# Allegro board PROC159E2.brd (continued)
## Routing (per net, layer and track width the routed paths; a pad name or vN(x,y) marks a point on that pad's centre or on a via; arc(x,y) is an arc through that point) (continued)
ICSSM_MII0_RXD3_ADD: length 27.5
  TOP w0.147: R536.1 76.94,70.68 76.53,71.09 76.52,71.09 76.49,71.11 75.8,71.11 v1(75.34,70.66)
  L08_SIG2 w0.091: v1(72.17,57.89) 70.63,57.89 70.28,58.24 70.28,64.26 68.91,65.63 68.91,71.68 69.33,72.1 70.54,72.1 71.37,71.27 73.53,71.27 73.66,71.13 73.66,70.99 73.79,70.86 73.98,70.86 74.12,70.99 74.12,71.13 74.25,71.27 74.74,71.27 v1(75.34,70.66)
  BOTTOM w0.147: v1(72.17,57.89) U82.35
ICSSM_MII0_RXD3_ON: length 58.2
  TOP w0.147: R480.1 85.23,78.27 85.43,78.46 v1(85.43,79.32)
  L03_SIG1 w0.091: v1(85.43,79.32) 85.93,78.82 85.93,78.03 85,77.09 85,75.9 85.93,74.96 85.93,74.61 86.79,73.75 86.79,71.06 86.36,70.62 86.36,68.44 85.96,68.04 84.56,68.04 84.46,67.93 84.46,67.78 84.56,67.67 85.82,67.67 85.93,67.57 85.93,67.41 85.82,67.31 84.56,67.31 84.46,67.2 84.46,67.05 84.56,66.94 85.5,66.94 85.93,66.51 85.93,65.8 85.57,65.44 82.61,65.44 82.49,65.55 82.49,65.77 82.61,65.89 85.38,65.89 85.52,66.03 85.52,66.25 85.38,66.39 82.31,66.39 82.12,66.57 81.13,66.57 79.72,67.97 79.72,69.59 79.17,70.14 77.46,70.14 77.06,69.73 77.06,69.35 75.85,68.14 74.03,68.14 70.27,64.38 70.27,58.12 70.73,57.66 70.99,57.66 v1(71.25,57.39)
  BOTTOM w0.147: U82.36 v1(71.25,57.39)
ICSSM_MII0_RXDV: length 17.3
  TOP w0.147: U87.34 73.79,58.39 73.41,58.02 73.41,57.87 73.22,57.68 72.91,57.68 72.78,57.81 72.78,58.04 73.42,58.68 73.42,58.94 73.27,59.08 72.78,59.08 72.62,58.93 72.62,58.58 72.43,58.39 72.01,58.39 71.51,58.89 71.04,58.89 70.71,58.56 70.71,58.22 70.58,58.09 70.39,58.09 70.27,58.22 70.27,58.77 70.56,59.07 70.56,59.25 70.41,59.4 70.19,59.4 70.01,59.22 70.01,59.04 69.6,58.63 67.76,58.63 67.58,58.45 67.22,58.45 66.96,58.71 66.96,58.93 67.1,59.07 67.3,59.07 67.42,59.19 67.42,59.31 67.29,59.45 66.31,59.45 66.18,59.31 v1(66.18,58.89)
  BOTTOM w0.147: U82.6 v1(66.18,58.89)
ICSSM_MII0_RXDV_ADD: length 27.9
  L08_SIG2 w0.091: v1(72.17,58.89) 70.98,58.89 70.55,59.32 70.55,64.38 69.18,65.74 69.18,70.81 69.64,71.26 70.78,71.26 71.91,70.14 75.91,70.14 76.38,69.67 v1(78.54,69.67)
  BOTTOM w0.147: v1(72.17,58.89) U82.33 ; R537.1 76.88,69.66 77.33,69.21 78.16,69.21 v1(78.54,69.67)
ICSSM_MII0_RXDV_ON: length 57.8
  TOP w0.147: R481.1 v1(97.63,94.93)
  L08_SIG2 w0.091: v1(97.63,94.93) 98.67,93.9 98.67,90.09 97.71,89.12 97.71,83.8 95.88,81.98 94.98,81.98 94.06,81.05 90.24,81.05 86.83,77.65 86.83,76.22 85.9,75.29 85.19,75.29 84.74,75.74 84.42,75.74 83.26,74.58 83.26,71.71 81.51,69.96 81.51,63.2 80.41,62.11 80.41,61.74 79.46,60.78 79.46,60.4 77.72,58.67 75.21,58.67 74.94,58.39 v1(71.25,58.39)
  BOTTOM w0.147: U82.34 v1(71.25,58.39)
ICSSM_MII0_RXER: length 16.6
  TOP w0.147: v1(64.5,59.39) 63.55,59.39 63.35,59.2 63.35,58.77 63.53,58.6 64.71,58.6 65.87,59.76 70.98,59.76 71.06,59.85 71.5,59.85 71.95,59.39 U87.32
  BOTTOM w0.147: U82.7 65.94,59.39 65.61,59.07 64.83,59.07 v1(64.5,59.39)
ICSSM_MII0_RXER_ADD: length 28
  L08_SIG2 w0.091: v1(78.54,68.68) 78.06,69.16 75.08,69.16 74.38,69.86 73.93,69.86 73.8,69.73 73.8,69.48 73.66,69.35 73.47,69.35 73.34,69.48 73.34,69.73 73.2,69.86 73.01,69.86 72.88,69.73 72.88,69.48 72.75,69.35 72.56,69.35 72.42,69.48 72.42,69.73 72.29,69.86 71.75,69.86 70.62,70.99 69.75,70.99 69.46,70.7 69.46,65.86 70.82,64.49 70.82,60.15 71.08,59.89 v1(72.17,59.89)
  BOTTOM w0.147: R538.1 76.88,68.67 77.33,68.22 78.16,68.22 v1(78.54,68.68) ; v1(72.17,59.89) U82.31
ICSSM_MII0_RXER_ON: length 57.5
  TOP w0.147: R482.1 v1(97.63,93.94)
  L08_SIG2 w0.091: v1(71.25,59.39) 72.62,59.39 72.72,59.29 72.72,58.71 72.83,58.61 72.98,58.61 73.09,58.71 73.09,59.29 73.2,59.39 74.84,59.39 75.23,59.78 77.43,59.78 78.76,61.1 79.06,61.1 79.48,61.53 79.48,62.06 79.76,62.35 80.39,62.35 81.25,63.2 81.25,70.07 83,71.82 83,74.63 84.37,76 84.9,76 85.37,75.54 85.76,75.54 86.61,76.39 86.61,77.71 90.15,81.26 93.94,81.26 94.89,82.2 95.72,82.2 97.47,83.95 97.47,89.27 98.39,90.2 98.39,93.76 98.21,93.94 v1(97.63,93.94)
  BOTTOM w0.147: U82.32 v1(71.25,59.39)
ICSSM_MII0_RXLINK: length 16.6
  TOP w0.147: U87.27 72.77,61.89 72.61,62.06 72.61,62.27 72.73,62.39 73.3,62.39 73.44,62.54 73.44,62.8 72.64,63.61 72.64,64.72 72.3,65.06 71.38,65.06 71.09,64.77 71.09,64.51 71.21,64.38 71.56,64.38 71.69,64.25 71.69,64.07 71.56,63.94 71.21,63.94 71.09,63.81 71.09,62.99 70.93,62.84 70.4,62.84 69.66,62.09 67.33,62.09 67.13,61.89 v1(66.18,61.89)
  BOTTOM w0.147: U82.12 v1(66.18,61.89)
ICSSM_MII0_RXLINK_ADD: length 27.5
  L08_SIG2 w0.091: v1(71.25,62.39) 71.25,64.45 69.73,65.97 69.73,70.39 69.98,70.64 70.58,70.64 72.25,68.98 74.46,68.98 75.25,68.18 75.76,68.18 76.36,68.79 77.78,68.79 78.38,68.18 78.73,68.18 78.98,68.44 78.98,69.62 79.12,69.76 79.27,69.76 79.38,69.65 79.38,67.54 v1(78.54,66.7)
  BOTTOM w0.147: U82.26 v1(71.25,62.39) ; v1(78.54,66.7) 78.16,66.23 77.33,66.23 76.88,66.69 R540.1
ICSSM_MII0_RXLINK_ON: length 57.5
  TOP w0.147: R484.1 v1(97.63,91.96)
  L08_SIG2 w0.091: v1(97.63,91.96) 97.63,90.23 96.91,89.51 96.91,85.15 94.9,83.14 94.9,82.73 93.81,81.64 89.99,81.64 85.77,77.42 85.15,77.42 82.5,74.76 82.5,72.03 80.75,70.28 80.75,65.5 80.66,65.41 79.94,65.41 79.83,65.3 79.83,65.15 79.94,65.05 80.57,65.05 80.75,64.87 80.75,64.21 80.4,63.86 78.79,63.86 78.11,63.19 74.92,63.19 74.82,63.08 74.82,61.39 74.71,61.28 74.56,61.28 74.45,61.39 74.45,63.08 74.34,63.19 73.68,63.19 73.46,62.97 73.46,62.6 73.36,62.49 72.72,62.49 72.61,62.39 72.61,62.24 72.72,62.13 73.36,62.13 73.46,62.02 73.46,61.55 73.24,61.33 72.39,61.33 72.17,61.55 v1(72.17,61.89)
  BOTTOM w0.147: v1(72.17,61.89) U82.27
ICSSM_MII0_TXCLK: length 15.7
  TOP w0.147: U85.3 v1(94.14,98.84)
  BOTTOM w0.147: v1(94.14,98.84) 94.6,98.38 94.6,97.12 93.54,96.06 86.65,96.06 86.41,96.3 86.08,96.3 85.91,96.47 85.91,97.06 85.73,97.24 85.49,97.24 85.32,97.06 85.32,96.47 85.14,96.3 84.79,96.3 84.59,96.5 U88.39
ICSSM_MII0_TXCLK_ADD: length 52.6
  TOP w0.147: U85.40 v1(91.35,96.55)
  L08_SIG2 w0.091: v1(68.45,81.7) 68.91,82.16 70.09,82.16 70.98,81.27 70.98,79.97 70.37,79.36 70.37,76.31 71.58,75.1 75.75,75.1 76.01,74.84 76.01,74.41 78.33,72.09 79.04,72.09 80.47,73.52 80.47,78 82.26,79.79 82.26,80.76 83.18,81.67 83.18,83.16 85.18,85.16 85.18,91.78 85.82,92.43 85.82,92.91 86.23,93.32 87.54,93.32 90.77,96.55 v1(91.35,96.55)
  BOTTOM w0.147: v1(68.45,81.7) 67.98,82.16 67.98,83 68.44,83.45 R520.1
ICSSM_MII0_TXCLK_ON: length 31
  TOP w0.147: R496.1 98.32,98.6 98.47,98.45 99.95,98.45 100.22,98.72 100.22,99.2 100.01,99.41 97.86,99.41 97.59,99.68 97.59,100.4 97.98,100.79 97.98,102.89 98.29,103.2 98.29,104.68 98.14,104.83 97.77,104.83 97.62,104.68 97.62,103.25 97.41,103.05 97.41,100.89 96.92,100.4 96.68,100.4 96.1,100.4 95.85,100.15 95.85,99.64 96.09,99.4 96.9,99.4 97.13,99.17 97.13,98.66 96.84,98.37 96.12,98.37 95.85,98.11 95.85,97.34 94.52,96.01 94.02,96.01 93.89,96.14 93.89,96.82 93.76,96.95 93.46,96.95 93.31,96.8 93.31,96.02 93.07,95.79 91.1,95.79 90.85,96.04 U85.39
ICSSM_MII0_TXD0: length 16.1
  TOP w0.147: v1(95.05,98.84) 94.55,99.34 U85.4
  BOTTOM w0.147: U88.38 86.22,97.84 86.44,97.62 86.44,96.73 86.82,96.36 90.49,96.36 91.06,96.92 91.06,97.19 90.25,98 90.25,98.49 90.56,98.8 93.43,98.8 93.94,99.31 94.58,99.31 v1(95.05,98.84)
ICSSM_MII0_TXD0_ADD: length 52.3
  TOP w0.147: U85.37 88.92,98.34 88.65,98.07 88.38,98.07 88.38,98.07 v1(88.15,97.84)
  L08_SIG2 w0.091: v1(88.15,97.84) 89.61,97.84 90.57,98.8 92.65,98.8 93.34,98.1 93.34,97.9 93.94,97.3 94.25,97.3 94.57,96.98 94.57,96.31 93.77,95.51 93.08,95.51 92.8,95.8 92.8,96.73 92.54,96.99 90.82,96.99 87.43,93.6 86.05,93.6 85.38,92.93 85.38,92.37 84.69,91.68 82.85,91.68 82.55,91.39 82.55,88.77 82.38,88.6 82.13,88.6 81.91,88.82 81.91,90.08 81.65,90.33 81.13,90.33 80.72,89.92 80.72,88.79 82.09,87.42 82.09,84.93 81.72,84.56 81.72,80.03 79.86,78.17 79.86,75.52 78.45,74.12 78.03,74.12 v1(77.49,74.65)
  BOTTOM w0.147: R521.1 v1(77.49,74.65)
ICSSM_MII0_TXD0_ON: length 30.6
  TOP w0.147: R497.1 99.09,102.62 98.95,102.48 98.71,102.48 98.57,102.34 98.57,102.18 98.74,102.01 99.26,102.01 99.44,101.84 99.44,101.59 99.26,101.42 98.74,101.42 98.57,101.25 98.57,100.6 98.74,100.43 99.52,100.43 99.73,100.63 99.73,101.12 100,101.38 100.91,101.38 101.05,101.24 101.05,100.96 100.88,100.79 100.44,100.79 100.26,100.62 100.26,100.38 100.44,100.21 100.88,100.21 101.05,100.04 101.05,99.46 100.88,99.29 100.69,99.29 100.52,99.12 100.52,98.88 100.7,98.7 100.88,98.7 101.05,98.53 101.05,96.79 100.59,96.33 97.3,96.33 97.05,96.58 97.05,97.17 96.84,97.38 96.38,97.38 96.31,97.38 96.08,97.16 96.08,96.48 95.94,96.33 95.41,96.33 94.58,95.49 90.89,95.49 90.1,96.28 90.1,96.52 90.34,96.76 90.34,97.01 90.16,97.18 89.92,97.18 89.68,96.94 89.44,96.94 89.18,97.19 89.18,97.6 89.42,97.84 U85.38
ICSSM_MII0_TXD1: length 15.6
  TOP w0.147: U85.5 v1(94.14,99.84)
  BOTTOM w0.147: v1(94.14,99.84) 93.68,99.84 92.94,99.1 90.32,99.1 89.96,98.73 89.96,97.88 90.61,97.22 90.61,96.9 90.37,96.65 87.2,96.65 86.86,96.99 86.86,97.25 87.03,97.42 87.43,97.42 87.6,97.59 87.6,97.84 87.43,98.01 87.03,98.01 86.86,98.18 86.86,98.52 86.55,98.84 U88.36
ICSSM_MII0_TXD1_ADD: length 52.3
  TOP w0.147: U85.35 88.86,99.34 88.56,99.04 88.35,99.04 v1(88.15,98.84)
  L08_SIG2 w0.091: v1(77.55,75.68) 78.09,75.13 79.06,75.13 79.58,75.66 79.58,78.28 81.45,80.15 81.45,84.67 81.82,85.05 81.82,87.3 80.44,88.68 80.44,90.03 81.02,90.61 81.96,90.61 82.28,90.92 82.28,92.21 82.77,92.7 84.5,92.7 85.78,93.99 87.31,93.99 90.58,97.26 92.65,97.26 93.07,96.84 93.07,96.12 93.4,95.79 93.66,95.79 94.3,96.43 94.3,96.87 94.14,97.03 93.78,97.03 93.03,97.78 90.2,97.78 89.76,97.35 87.89,97.35 87.67,97.56 87.67,98.04 87.89,98.26 89.62,98.26 89.78,98.42 89.78,98.69 89.64,98.84 v1(88.15,98.84)
  BOTTOM w0.147: v1(77.55,75.68) 77.49,75.68 77.49,75.68 R522.1
ICSSM_MII0_TXD1_ON: length 30.7
  TOP w0.147: R498.1 99.09,104.01 99.09,103.69 99.28,103.51 100.81,103.51 101.35,102.98 101.35,102.57 101.17,102.39 100.26,102.39 100.09,102.22 100.09,101.98 100.26,101.8 101.17,101.8 101.35,101.63 101.35,96.67 100.71,96.03 95.53,96.03 94.7,95.2 89.97,95.2 89.68,95.49 89.68,95.73 89.76,95.8 89.76,96.05 89.58,96.22 89.34,96.22 89.26,96.15 89.02,96.15 88.85,96.32 88.85,96.56 88.92,96.64 88.92,96.88 88.75,97.05 88.51,97.05 88.43,96.98 88.19,96.98 87.63,97.54 87.63,98.06 87.95,98.38 88.51,98.38 88.96,98.84 U85.36
ICSSM_MII0_TXD2: length 15.7
  TOP w0.147: U85.6 94.55,100.34 v1(95.05,99.84)
  BOTTOM w0.147: v1(95.05,99.84) 94.55,100.34 93.4,100.34 93.07,100 90.46,100 89.6,99.14 89.6,97.42 89.44,97.26 88.82,97.26 88.67,97.41 88.67,98.02 88.37,98.32 87.69,98.32 87.12,98.89 87.12,99.5 86.79,99.84 U88.34
ICSSM_MII0_TXD2_ADD: length 52.3
  TOP w0.147: U85.33 88.65,100.34 v1(88.15,99.84)
  L08_SIG2 w0.091: v1(77.55,76.67) 77.71,76.67 78.15,76.22 78.65,76.22 79.31,76.88 79.31,78.4 80.06,79.14 80.06,79.3 79.93,79.43 79.93,79.58 80.03,79.68 80.19,79.68 80.31,79.55 80.47,79.55 80.57,79.66 80.57,79.81 80.44,79.94 80.44,80.09 80.55,80.2 80.7,80.2 80.83,80.07 80.98,80.07 81.17,80.26 81.17,80.78 81.06,80.89 80.33,80.89 80.22,80.99 80.22,81.15 80.33,81.25 81.06,81.25 81.17,81.36 81.17,81.51 81.06,81.62 80.33,81.62 80.22,81.73 80.22,81.88 80.33,81.98 81.06,81.98 81.17,82.09 81.17,82.24 81.06,82.35 80.33,82.35 80.22,82.46 80.22,82.61 80.33,82.72 81.06,82.72 81.17,82.82 81.17,82.97 81.06,83.08 80.33,83.08 80.22,83.19 80.22,83.34 80.33,83.45 81.06,83.45 81.17,83.55 81.17,83.71 81.06,83.81 80.33,83.81 80.22,83.92 80.22,84.07 80.33,84.18 81.06,84.18 81.17,84.29 81.17,84.44 81.06,84.54 80.33,84.54 80.22,84.65 80.22,84.8 80.33,84.91 81.06,84.91 81.17,85.02 81.17,85.17 81.06,85.28 80.33,85.28 80.22,85.38 80.22,85.53 80.33,85.64 81.06,85.64 81.17,85.75 81.17,86.19 79.91,87.45 79.91,89.89 80.91,90.88 81.85,90.88 82,91.04 82,92.33 82.65,92.98 84.38,92.98 85.67,94.26 87.12,94.26 87.53,94.67 87.53,94.82 87.32,95.03 87.32,95.18 87.43,95.28 87.58,95.28 87.78,95.08 87.94,95.08 88.04,95.19 88.04,95.34 87.84,95.54 87.84,95.69 87.94,95.8 88.1,95.8 88.3,95.6 88.45,95.6 88.56,95.7 88.56,95.85 88.35,96.06 88.35,96.21 88.46,96.32 88.61,96.32 88.82,96.11 88.97,96.11 89.43,96.57 89.43,96.87 89.23,97.07 87.78,97.07 87.4,97.45 87.4,99.08 v1(88.15,99.84)
  BOTTOM w0.147: v1(77.55,76.67) 77.49,76.67 77.49,76.67 R523.1
ICSSM_MII0_TXD2_ON: length 31
  TOP w0.147: R499.1 99.09,104.69 99.27,104.51 100.77,104.51 101.64,103.64 101.64,96.55 100.83,95.74 95.66,95.74 94.82,94.9 89.75,94.9 87.31,97.35 87.31,98.94 87.7,99.33 88.31,99.33 88.81,99.84 U85.34
ICSSM_MII0_TXD3: length 15.7
  TOP w0.147: U85.7 v1(94.14,100.84)
  BOTTOM w0.147: v1(94.14,100.84) 94.34,100.63 94.62,100.63 94.78,100.8 94.78,101.03 94.29,101.51 93.35,101.51 93.2,101.36 93.2,100.84 92.7,100.33 90.37,100.33 90.23,100.18 89.98,100.18 89.72,100.44 89.48,100.44 89.3,100.27 89.3,100.03 89.56,99.77 89.56,99.52 89.3,99.26 89.3,98.63 89.16,98.48 88.84,98.48 88.67,98.65 88.67,99.1 88.44,99.33 87.87,99.33 86.88,100.32 86.88,100.58 86.63,100.84 U88.32
ICSSM_MII0_TXD3_ADD: length 52.5
  TOP w0.147: U85.31 88.65,101.34 v1(88.15,100.84)
  L08_SIG2 w0.091: v1(78.26,77.66) 79.03,78.43 79.03,78.68 79.44,79.08 79.44,79.88 79.89,80.33 79.89,80.85 79.78,80.96 79.28,80.96 79.17,81.06 79.17,81.22 79.28,81.32 79.78,81.32 79.89,81.43 79.89,81.58 79.78,81.69 79.28,81.69 79.17,81.8 79.17,81.95 79.28,82.05 79.78,82.05 79.89,82.16 79.89,82.31 79.78,82.42 79.28,82.42 79.17,82.53 79.17,82.68 79.28,82.79 79.78,82.79 79.89,82.89 79.89,83.04 79.78,83.15 79.28,83.15 79.17,83.26 79.17,83.41 79.28,83.52 79.78,83.52 79.89,83.62 79.89,83.78 79.78,83.88 79.28,83.88 79.17,83.99 79.17,84.14 79.28,84.25 79.78,84.25 79.89,84.36 79.89,84.51 79.78,84.61 79.28,84.61 79.17,84.72 79.17,84.87 79.28,84.98 79.78,84.98 79.89,85.09 79.89,85.24 79.78,85.35 79.28,85.35 79.17,85.45 79.17,85.6 79.28,85.71 79.78,85.71 79.89,85.82 79.89,85.97 79.78,86.08 79.28,86.08 79.17,86.18 79.17,86.34 79.28,86.44 79.78,86.44 79.89,86.55 79.89,87.09 79.8,87.18 79.64,87.34 79.64,87.7 79.53,87.81 79.15,87.81 79.04,87.92 79.04,88.07 79.15,88.18 79.53,88.18 79.64,88.28 79.64,88.43 79.53,88.54 79.15,88.54 79.04,88.65 79.04,88.8 79.15,88.91 79.53,88.91 79.64,89.01 79.64,89.17 79.53,89.27 79.15,89.27 79.04,89.38 79.04,89.53 79.15,89.64 79.53,89.64 79.64,89.75 79.64,90.05 79.53,90.15 79.22,90.15 79.12,90.26 79.12,90.41 79.22,90.52 79.53,90.52 79.64,90.63 79.64,90.78 79.53,90.88 79.22,90.88 79.12,90.99 79.12,91.14 79.22,91.25 79.53,91.25 79.64,91.36 79.64,91.73 79.81,91.9 79.96,91.9 80.09,91.76 80.09,90.96 80.19,90.86 80.4,90.86 80.52,90.98 80.52,92.23 80.69,92.4 80.92,92.4 81.06,92.25 81.06,91.33 81.23,91.16 81.53,91.16 81.73,91.36 81.73,92.44 82.54,93.25 84.27,93.25 85.55,94.54 86.66,94.54 86.91,94.8 86.91,95.32 86.7,95.54 86.7,96.04 86.92,96.26 87.95,96.26 88.08,96.39 88.08,96.58 87.96,96.7 87.56,96.7 87.12,97.13 87.12,99.81 v1(88.15,100.84)
  BOTTOM w0.147: v1(78.26,77.66) 78.25,77.67 R524.1
ICSSM_MII0_TXD3_ON: length 30.9
  TOP w0.147: U85.32 v1(89.06,100.84) ; R500.1 v1(98.31,106)
  BOTTOM w0.147: v1(98.31,106) 98.31,106.45 98.77,106.91 102.1,106.91 102.85,106.16 102.85,105.53 102.67,105.36 101.53,105.36 101.35,105.19 101.35,104.94 101.53,104.77 102.67,104.77 102.85,104.6 102.85,104.36 102.67,104.18 101.53,104.18 101.35,104.01 101.35,103.77 101.53,103.59 102.67,103.59 102.85,103.42 102.85,102.65 102.07,101.87 95.1,101.87 94.42,102.55 93.85,102.55 92.61,101.31 89.54,101.31 v1(89.06,100.84)
ICSSM_MII0_TXEN: length 16
  TOP w0.147: U85.2 94.55,98.34 v1(95.05,97.84)
  BOTTOM w0.147: U88.41 83.59,96.34 83.92,96.01 86.29,96.01 86.55,95.75 93.68,95.75 95.05,97.12 v1(95.05,97.84)
ICSSM_MII0_TXEN_ADD: length 52.5
  TOP w0.147: U85.42 v1(92.35,96.55)
  L08_SIG2 w0.091: v1(69.44,81.7) 69.76,81.38 69.76,76.21 72.27,73.7 74.24,73.7 74.68,74.13 75.63,74.13 76.71,73.06 76.71,72.42 77.96,71.18 78.33,71.18 78.46,71.31 78.76,71.31 80.74,73.29 80.74,77.7 82.44,79.41 82.44,80.68 83.36,81.6 83.36,83.08 85.36,85.08 85.36,91.5 86.17,92.31 87.12,92.31 90.4,95.6 91.4,95.6 v1(92.35,96.55)
  BOTTOM w0.147: R519.1 69.43,83.45 68.98,83 68.98,82.16 v1(69.44,81.7)
ICSSM_MII0_TXEN_ON: length 30.6
  TOP w0.147: U85.41 91.85,96.31 92.08,96.08 92.63,96.08 92.98,96.43 92.98,97.08 93.19,97.29 95.19,97.29 95.54,97.64 95.54,100.43 95.8,100.69 96.8,100.69 97.12,101.02 97.12,103.17 97.32,103.37 97.32,105.5 97.62,105.8 97.62,106.29 98.09,106.76 101.46,106.76 101.83,106.39 101.83,105.83 101.51,105.51 98.76,105.51 98.58,105.33 98.58,103.08 98.27,102.77 98.27,100.67 97.88,100.28 97.88,100.07 98.06,99.9 R495.1
ICSSM_MII1_COL: length 24
  TOP w0.147: U84.4 94.55,86.35 v1(95.05,85.85)
  BOTTOM w0.147: v1(95.05,85.85) 95.05,86.44 94.6,86.89 94.6,87.58 95.55,88.53 95.55,93.87 94.7,94.73 92.91,94.73 92.64,94.45 92.64,93.72 92.05,93.13 90.69,93.13 90.15,93.67 87.44,93.67 87.2,93.43 87.2,92.52 86.83,92.15 86.83,91.65 86.53,91.35 U89.25
ICSSM_MII1_COL_ADD: length 47.4
  TOP w0.147: U84.38 v1(89.06,84.85) ; R509.1 v1(71.42,82.81)
  L08_SIG2 w0.091: v1(71.42,82.81) 70.53,83.7 68.42,83.7 67.82,83.1 67.82,81.26 69.02,80.06 69.02,74.8 71.64,72.18 75.54,72.18 75.77,71.95 75.77,71.42 76.07,71.12 76.54,71.12 77.43,70.24 78.86,70.24 81.28,72.66 81.28,77.3 82.96,78.98 83.5,78.98 84.05,78.43 85.16,78.43 86.39,79.66 86.39,81.91 88.44,83.96 88.44,84.23 v1(89.06,84.85)
ICSSM_MII1_COL_ON: length 23.4
  TOP w0.147: v1(89.06,83.85) 88.56,84.35 88.56,85.07 88.84,85.35 U84.37
  L08_SIG2 w0.091: v1(96.56,96.93) 94.6,94.97 90.92,94.97 90.06,94.1 90.06,88.27 89.5,87.71 89.5,84.28 v1(89.06,83.85)
  BOTTOM w0.147: v1(96.56,96.93) 97.07,97.43 97.81,97.43 98.31,96.93 R501.1
ICSSM_MII1_CRS: length 22.2
  TOP w0.147: U84.5 94.67,86.85 v1(95.05,87.23)
  BOTTOM w0.147: v1(95.05,87.23) 95.84,88.02 95.84,94 94.82,95.02 92.79,95.02 92.34,94.58 92.34,93.85 91.93,93.43 90.81,93.43 90.27,93.97 87.32,93.97 86.9,93.55 86.9,92.65 86.6,92.35 U89.23
ICSSM_MII1_CRS_ADD: length 45.6
  TOP w0.147: R510.1 v1(70.43,82.81) ; U84.36 v1(89.06,85.85)
  L08_SIG2 w0.091: v1(70.43,82.81) 69.88,83.36 68.36,83.36 68.01,83.01 68.01,81.44 69.29,80.16 69.29,74.91 71.08,73.12 75.51,73.12 75.85,72.78 75.85,72.46 76.1,72.21 76.35,72.21 77.75,70.81 78.22,70.81 78.51,71.1 78.96,71.1 81.03,73.17 81.03,77.42 82.87,79.26 83.62,79.26 84.22,78.67 84.68,78.67 84.96,78.95 84.96,79.51 85.21,79.76 85.61,79.76 86.06,80.22 86.06,82.06 87.68,83.67 87.68,84.47 v1(89.06,85.85)
ICSSM_MII1_CRS_ON: length 19.4
  TOP w0.147: U84.35 89.21,86.35 89.06,86.49 v1(89.06,86.85)
  L08_SIG2 w0.091: v1(96.56,97.92) 93.88,95.24 90.81,95.24 89.97,94.4 89.79,94.22 89.79,88.47 89.06,87.75 v1(89.06,86.85)
  BOTTOM w0.147: R502.1 98.31,97.92 97.81,98.42 97.07,98.42 v1(96.56,97.92)
ICSSM_MII1_RXCLK: length 21.4
  TOP w0.147: v1(87.29,89.85) 88.07,89.07 88.07,88.8 88.2,88.67 88.42,88.67 88.55,88.54 88.55,88.35 88.42,88.22 88.2,88.22 88.07,88.1 88.07,87.91 88.2,87.78 88.42,87.78 88.55,87.65 88.55,87.47 88.42,87.34 88.2,87.34 88.07,87.21 88.07,87.03 88.2,86.9 88.42,86.9 88.55,86.77 88.55,86.59 88.42,86.46 88.2,86.46 88.07,86.33 88.07,86.14 88.2,86.02 88.42,86.02 88.55,85.89 88.55,85.7 88.42,85.57 88.2,85.57 88.07,85.44 88.07,84.07 88.93,83.21 89.13,83.21 89.66,82.68 90.02,82.68 90.15,82.81 90.15,82.89 90.28,83.02 90.47,83.02 90.6,82.89 90.6,82.81 90.73,82.68 90.91,82.68 91.04,82.81 91.04,82.89 91.17,83.02 91.35,83.02 91.48,82.89 91.48,82.81 91.61,82.68 93.23,82.68 94.61,84.07 94.61,84.89 94.16,85.35 U84.2
  BOTTOM w0.147: U89.29 86.79,89.35 v1(87.29,89.85)
ICSSM_MII1_RXCLK_ADD: length 46.1
  TOP w0.147: U84.41 91.85,83.32 92.15,83.01 92.81,83.01 v1(93.35,83.56) ; R531.1 v1(77.6,67.69)
  L08_SIG2 w0.091: v1(77.6,67.69) 77.11,67.2 77.11,66.34 77.56,65.88 79,65.88 79.95,66.83 79.95,70.58 81.76,72.39 81.76,74.85 84.91,77.99 85.41,77.99 89.68,82.26 91.08,82.26 91.29,82.46 91.29,82.8 90.83,83.26 90.83,83.81 91.06,84.03 92.26,84.03 93.51,85.28 93.51,89.64 93.6,89.73 93.86,89.73 93.95,89.64 93.95,85.18 93.35,84.58 v1(93.35,83.56)
ICSSM_MII1_RXCLK_ON: length 17.7
  TOP w0.147: U84.42 v1(92.35,83.56)
  L08_SIG2 w0.091: v1(96.39,92.95) 96.11,93.23 95.89,93.23 95.57,92.92 95.57,90.18 95.26,89.87 94.81,89.87 94.23,89.29 94.23,85.05 93.63,84.45 93.63,84.11 93.78,83.95 93.78,83.31 93.24,82.77 92.35,82.77 92.1,83.02 92.1,83.31 v1(92.35,83.56)
  BOTTOM w0.147: v1(96.39,92.95) 96.85,92.95 97.35,93.46 97.89,93.46 98.4,92.95 R491.1
ICSSM_MII1_RXD0: length 21.3
  TOP w0.147: U84.11 94.55,89.85 v1(95.05,90.35)
  BOTTOM w0.147: v1(95.05,90.35) 95.05,88.77 94.25,87.96 94.25,86.18 93.88,85.81 90.47,85.81 90.28,85.62 90.28,84.25 89.41,83.38 88.56,83.38 88.43,83.51 88.43,83.84 88.3,83.97 88.11,83.97 87.98,83.84 87.98,83.51 87.85,83.38 87.43,83.38 87.06,83.01 83.89,83.01 83.59,83.3 U89.41
ICSSM_MII1_RXD0_ADD: length 46.3
  TOP w0.147: U84.29 88.65,89.35 87.89,90.1 87.89,91.05 87.44,91.5 87.44,93.54 87.09,93.89 86.13,93.89 85.84,93.6 85.84,90.76 85.67,90.59 85.42,90.59 85.25,90.76 85.25,93.28 85.08,93.45 83.04,93.45 81.42,95.07 v1(81.42,96.02)
  BOTTOM w0.147: R525.1 76.94,73.97 77.07,74.1 78.45,74.1 78.99,74.64 78.99,78.58 78.55,79.03 78.55,82.93 76.85,84.63 76.85,90.4 81.42,94.97 v1(81.42,96.02)
ICSSM_MII1_RXD0_ON: length 17.7
  TOP w0.147: U84.28 v1(89.06,89.85)
  L08_SIG2 w0.091: v1(84.46,82.11) 84.46,82.76 87.04,85.34 87.04,85.49 86.75,85.77 86.75,85.93 86.86,86.03 87.01,86.03 87.3,85.75 87.45,85.75 88.06,86.37 88.06,86.51 87.96,86.62 87,86.62 86.9,86.73 86.9,86.88 87,86.99 87.96,86.99 88.06,87.09 88.06,87.24 87.96,87.35 87,87.35 86.9,87.46 86.9,87.61 87,87.72 87.96,87.72 88.06,87.82 88.06,88.73 88.17,88.84 88.51,88.84 88.62,88.95 88.62,89.1 88.51,89.21 88.17,89.21 88.06,89.31 88.06,89.64 88.27,89.85 v1(89.06,89.85)
  BOTTOM w0.147: R485.1 v1(84.46,82.11)
ICSSM_MII1_RXD1: length 21.4
  TOP w0.147: U84.12 v1(94.14,90.35)
  BOTTOM w0.147: v1(94.14,90.35) 94.61,89.87 94.61,89.1 93.95,88.44 93.95,88.16 93.82,88.03 93.45,88.03 93.32,87.9 93.32,87.72 93.45,87.59 93.82,87.59 93.95,87.46 93.95,87.28 93.82,87.15 93.45,87.15 93.32,87.02 93.32,86.84 93.45,86.71 93.82,86.71 93.95,86.58 93.95,86.3 93.76,86.11 90.35,86.11 89.99,85.74 89.99,84.69 89.63,84.34 88.7,84.34 88.57,84.46 88.57,84.86 88.44,84.99 88.25,84.99 88.13,84.86 88.13,84.46 88,84.34 87.81,84.34 87.68,84.46 87.68,84.86 87.55,84.99 87.37,84.99 87.24,84.86 87.24,84.46 87.11,84.34 86.73,84.34 86.19,83.79 85.94,83.79 85.82,83.92 85.82,84.16 85.69,84.29 85.5,84.29 85.37,84.16 85.37,83.92 85.24,83.79 84.94,83.79 84.59,84.14 U89.39
ICSSM_MII1_RXD1_ADD: length 46.6
  TOP w0.147: v1(82.09,95.4) 82.09,94.94 82.97,94.06 84.95,94.06 85.84,94.95 85.84,97.16 86.03,97.36 86.25,97.36 86.42,97.18 86.42,96.11 86.59,95.94 87.26,95.94 87.43,95.77 87.43,95.52 87.26,95.35 86.59,95.35 86.42,95.18 86.42,94.88 86.64,94.66 87.61,94.66 87.83,94.45 87.83,91.72 88.31,91.23 88.31,90.69 88.65,90.35 U84.27
  BOTTOM w0.147: R526.1 76.94,72.98 77.13,73.18 78.61,73.18 79.34,73.91 79.34,78.69 78.86,79.17 78.86,83.03 77.2,84.69 77.2,90.29 82.09,95.18 v1(82.09,95.4)
ICSSM_MII1_RXD1_ON: length 17.6
  TOP w0.147: U84.26 v1(89.06,90.85)
  L08_SIG2 w0.091: v1(89.06,90.85) 88.57,90.85 87.76,90.04 87.76,88.98 87.57,88.79 87.03,88.79 86.83,88.99 86.83,90.14 86.66,90.32 86.04,90.32 85.94,90.22 85.94,84.82 83.93,82.81 83.93,81.65 v1(84.46,81.12)
  BOTTOM w0.147: R486.1 v1(84.46,81.12)
ICSSM_MII1_RXD2: length 21.5
  TOP w0.147: v1(95.05,91.35) 94.55,90.85 U84.13
  BOTTOM w0.147: v1(95.05,91.35) 94.56,90.86 93.91,90.86 92.95,89.89 92.95,89.68 93.08,89.55 94.17,89.55 94.3,89.42 94.3,89.24 94.17,89.11 93.57,89.11 93.36,88.89 93.36,88.49 92.95,88.08 92.95,87.23 92.74,87.02 90.6,87.02 90.32,87.31 89.95,87.31 89.7,87.06 89.7,86.67 89.95,86.41 89.95,86.13 89.81,85.99 89.58,85.99 89.24,86.32 88.73,86.32 88.63,86.22 87.69,86.22 87.56,86.09 87.56,85.9 87.69,85.77 88.45,85.77 88.6,85.63 88.6,85.44 88.49,85.33 87.07,85.33 86.58,84.85 U89.38
ICSSM_MII1_RXD2_ADD: length 46.6
  TOP w0.147: v1(83.09,94.89) 83.09,95.89 83.26,96.06 83.47,96.06 83.64,95.89 83.64,94.56 83.84,94.36 84.83,94.36 85.49,95.02 85.49,97.47 85.87,97.84 86.53,97.84 86.72,97.65 86.72,97.1 88.21,95.61 88.21,92.02 88.88,91.35 U84.25
  BOTTOM w0.147: v1(83.09,94.89) 82.58,94.89 82.29,94.6 81.94,94.6 77.55,90.21 77.55,84.76 79.17,83.14 79.17,79.32 79.7,78.8 79.7,72.88 78.83,72.02 78.48,72.02 78.38,72.12 77.07,72.12 76.94,71.99 R527.1
ICSSM_MII1_RXD2_ON: length 18.2
  TOP w0.147: U84.24 v1(89.06,91.85)
  L08_SIG2 w0.091: v1(84.46,80.09) 83.66,80.89 83.66,82.99 85.66,85 85.66,90.83 86.12,91.28 87.46,91.28 88.2,92.03 88.43,92.03 88.6,91.85 88.6,91.49 88.74,91.35 88.94,91.35 89.06,91.47 v1(89.06,91.85)
  BOTTOM w0.147: R487.1 v1(84.46,80.09)
ICSSM_MII1_RXD3: length 21.3
  TOP w0.147: U84.14 v1(94.14,91.35)
  BOTTOM w0.147: v1(94.14,91.35) 93.68,91.35 93.53,91.19 93.06,91.19 92.89,91.02 92.89,90.79 92.65,90.55 90.47,90.55 90.26,90.34 90.26,89.65 90.41,89.5 92.51,89.5 92.94,89.06 92.94,88.59 92.54,88.18 90.08,88.18 89.94,88.05 89.94,87.75 89.79,87.6 89.5,87.6 89.34,87.76 89.34,88.09 89.2,88.24 88.92,88.24 88.69,88.01 88.69,87.83 88.95,87.57 88.95,87.39 88.82,87.26 88.64,87.26 88.38,87.52 88.2,87.52 88.07,87.39 88.07,87.2 88.33,86.95 88.33,86.76 88.2,86.63 88.01,86.63 87.76,86.89 87.57,86.89 87.26,86.58 87.26,85.78 87.11,85.63 86.77,85.63 86.55,85.85 U89.36
ICSSM_MII1_RXD3_ADD: length 46.7
  TOP w0.147: v1(84.09,94.89) 85.2,95.99 85.2,99.36 85.66,99.83 86.67,99.83 87.01,99.49 87.01,97.22 88.5,95.74 88.5,92.66 88.81,92.35 U84.23
  BOTTOM w0.147: R528.1 76.94,71 77.07,71.13 78.53,71.13 80.05,72.65 80.05,78.91 79.49,79.47 79.49,83.24 77.9,84.83 77.9,90.13 81.94,94.17 83.37,94.17 v1(84.09,94.89)
ICSSM_MII1_RXD3_ON: length 18
  TOP w0.147: U84.22 v1(89.06,92.85)
  L08_SIG2 w0.091: v1(84.46,79.1) 84.46,79.48 84.96,79.98 84.96,82.87 88.54,86.46 88.54,87.71 89.51,88.68 89.51,92.62 89.28,92.85 v1(89.06,92.85)
  BOTTOM w0.147: R488.1 84.07,78.7 v1(84.46,79.1)
ICSSM_MII1_RXDV: length 21.6
  TOP w0.147: U84.15 94.55,91.85 v1(95.05,92.35)
  BOTTOM w0.147: U89.34 87.02,86.85 88.17,87.99 88.17,91.09 88.3,91.22 88.5,91.22 88.61,91.12 88.61,89.55 88.77,89.39 89.35,89.39 89.52,89.56 89.52,90.96 90.14,91.59 92.63,91.59 92.63,91.58 93.37,91.58 93.59,91.8 94.25,91.8 94.5,92.05 94.5,92.06 94.59,92.16 94.59,93.63 94.72,93.75 94.94,93.75 95.05,93.63 v1(95.05,92.35)
ICSSM_MII1_RXDV_ADD: length 46.3
  TOP w0.147: v1(78.06,94.93) 78.24,94.74 78.24,85.77 79.34,84.67 79.34,79.07 79.78,78.63 79.78,72.08 79.14,71.43 79.14,70.4 78.9,70.16 78.08,70.16 77.6,69.67 R529.1 ; U84.21 v1(90.85,94.14)
  BOTTOM w0.147: v1(90.85,94.14) 90.43,94.56 86.57,94.56 85.71,95.42 82.95,95.42 81.85,96.51 79.61,96.51 79.31,96.22 79.31,95.82 79.5,95.63 79.98,95.63 80.28,95.33 80.28,94.8 79.85,94.37 79.33,94.37 78.77,94.93 v1(78.06,94.93)
ICSSM_MII1_RXDV_ON: length 18.2
  TOP w0.147: U84.20 91.35,94.38 91.56,94.59 95.28,94.59 96.14,95.44 100.27,95.44 100.55,95.17 100.55,94.7 100.27,94.42 96.91,94.42 v1(96.39,94.94)
  BOTTOM w0.147: v1(96.39,94.94) 96.85,94.94 97.35,95.44 97.89,95.44 98.4,94.93 R489.1
ICSSM_MII1_RXER: length 21.4
  TOP w0.147: U84.16 v1(94.14,92.35)
  BOTTOM w0.147: v1(94.14,92.35) 94.13,92.34 93.52,92.34 93.07,91.89 90.53,91.89 90.17,92.25 90.17,93.07 90.02,93.23 89.69,93.23 89.52,93.06 89.52,91.47 89.38,91.32 88.91,91.32 88.5,91.73 88.5,93.19 88.31,93.38 88.04,93.38 87.87,93.21 87.87,92.31 87.74,92.19 87.31,92.19 87.19,92.06 87.19,91.87 87.31,91.74 87.74,91.74 87.87,91.61 87.87,89.48 87.74,89.35 87.34,89.35 87.21,89.22 87.21,89.04 87.34,88.91 87.74,88.91 87.87,88.78 87.87,88.25 87.47,87.85 U89.32
ICSSM_MII1_RXER_ADD: length 46.5
  TOP w0.147: v1(78.06,95.93) 78.6,95.39 78.6,85.91 79.69,84.81 79.69,79.21 80.14,78.77 80.14,71.93 79.47,71.26 79.47,69.89 78.72,69.14 78.06,69.14 77.6,68.68 R530.1 ; U84.19 v1(91.85,94.14)
  BOTTOM w0.147: v1(91.85,94.14) 91.13,94.85 86.69,94.85 85.83,95.71 83.07,95.71 81.85,96.93 79.06,96.93 v1(78.06,95.93)
ICSSM_MII1_RXER_ON: length 18.3
  TOP w0.147: U84.18 92.35,94.01 92.64,94.3 92.96,94.3 93.13,94.12 93.13,93.7 93.3,93.53 93.55,93.53 93.72,93.7 93.72,94.12 93.89,94.3 94.41,94.3 94.64,94.06 94.64,93 94.81,92.83 95.05,92.83 95.24,93.02 95.24,94.06 95.37,94.19 95.65,94.19 95.81,94.03 95.81,92.25 95.55,91.99 95.55,90.92 95.75,90.72 96.71,90.72 96.86,90.87 96.86,93.48 v1(96.39,93.95)
  BOTTOM w0.147: R490.1 98.4,93.94 97.89,94.45 97.35,94.45 96.85,93.95 v1(96.39,93.95)
ICSSM_MII1_RXLINK: length 21.7
  TOP w0.147: v1(87.29,90.85) 86.84,90.39 86.84,89.57 87.78,88.63 87.78,83.88 88.35,83.3 88.35,82.51 88.71,82.15 93.15,82.15 94.95,83.95 94.95,85.04 94.14,85.85 U84.3
  BOTTOM w0.147: U89.27 86.79,90.35 v1(87.29,90.85)
ICSSM_MII1_RXLINK_ADD: length 46.2
  TOP w0.147: R532.1 v1(77.6,66.7) ; v1(90.35,83.56) 90.85,84.06 U84.39
  L08_SIG2 w0.091: v1(77.6,66.7) 78.14,66.16 78.89,66.16 79.68,66.95 79.68,70.67 81.52,72.51 81.52,76.11 83.59,78.18 85.24,78.18 89.51,82.44 90.52,82.44 90.68,82.6 90.68,82.85 90.57,82.96 89.96,82.96 89.77,83.15 89.77,87.53 89.93,87.7 90.09,87.7 90.23,87.56 90.23,86.29 90.6,85.93 92.5,85.93 92.87,86.29 92.87,88.45 92.96,88.54 93.14,88.54 93.24,88.45 93.24,85.41 92.27,84.45 90.7,84.45 90.35,84.1 v1(90.35,83.56)
ICSSM_MII1_RXLINK_ON: length 17.7
  TOP w0.147: U84.40 v1(91.35,83.56)
  L08_SIG2 w0.091: v1(91.35,83.56) 91.35,83.23 92.28,82.3 93.27,82.3 94.07,83.1 94.07,83.58 95.13,84.64 95.13,85.07 94.57,85.62 94.57,89.13 95.01,89.57 95.57,89.57 95.9,89.89 95.9,91.47 v1(96.39,91.96)
  BOTTOM w0.147: v1(96.39,91.96) 96.85,91.96 97.35,92.47 97.89,92.47 98.4,91.96 R492.1
ICSSM_MII1_TXCLK: length 10.5
  TOP w0.147: U85.12 v1(94.14,103.34)
  L03_SIG1 w0.091: v1(94.14,103.34) 94.14,103.65 93.36,104.42 93.36,105.27 93.24,105.39 93.02,105.39 92.91,105.28 92.91,105.1 92.65,104.84 90.65,104.84 89.43,106.06 89.15,106.06 88.79,106.42 v1(88.79,107.46)
  BOTTOM w0.147: R1399.1 v1(88.79,107.46)
ICSSM_MII1_TXCLK_ADD: length 46.9
  TOP w0.147: v1(69.56,99.82) 70.34,100.59 74.89,100.59 76.06,101.76 76.06,103.05 80.32,107.3 82.19,107.3 82.87,106.62 86.9,106.62 87.56,105.96 87.56,103.65 87.88,103.34 U85.27 ; R512.1 v1(68.45,82.81)
  L03_SIG1 w0.091: v1(68.45,82.81) 68.45,88.93 69.53,90.02 69.53,92.99 71.53,94.98 71.53,96.75 70.48,97.8 70.48,98.9 v1(69.56,99.82)
ICSSM_MII1_TXCLK_ON: length 19.9
  TOP w0.147: U85.26 v1(89.06,103.84)
  L08_SIG2 w0.091: v1(96.56,98.91) 97.7,100.04 97.7,101.8 97.25,102.24 96.23,102.24 95.81,102.66 95.81,104.51 95.5,104.83 93.53,104.83 93.24,104.54 93.24,102.86 92.8,102.42 90.48,102.42 v1(89.06,103.84)
  BOTTOM w0.147: R504.1 97.82,99.41 97.07,99.41 v1(96.56,98.91)
ICSSM_MII1_TXD0: length 15.4
  TOP w0.147: U85.13 94.55,103.84 v1(95.05,104.34)
  BOTTOM w0.147: v1(95.05,104.34) 95.43,104.34 95.9,103.87 95.9,102.37 95.7,102.17 95.21,102.17 94.54,102.84 93.73,102.84 93.55,102.67 93.41,102.52 89.48,102.52 89.29,102.34 U88.29
ICSSM_MII1_TXD0_ADD: length 46.9
  TOP w0.147: R513.1 76.86,74.86 77.18,75.17 77.79,75.17 v1(78.31,74.65) ; v1(88.15,105.34) 88.15,104.68 88.49,104.34 U85.25
  L08_SIG2 w0.091: v1(88.15,105.34) 88.2,105.39 88.2,106.34 87.95,106.59 87.59,106.59 87.33,106.33 87.33,105.29 87.02,104.98 86.86,104.98 86.51,105.34 86.09,105.34 85.29,104.54 85.29,104.05 84.69,103.45 82.45,103.45 81.66,102.67 80.72,102.67 79.58,101.54 79.58,95.23 77.94,93.58 77.94,80.23 76.39,78.69 76.39,77.7 76.58,77.51 76.83,77.26 76.83,76.38 77.11,76.1 77.11,75.39 77.37,75.13 77.64,75.13 78.13,74.65 v1(78.31,74.65)
ICSSM_MII1_TXD0_ON: length 20.1
  TOP w0.147: v1(96.56,103.03) 97.03,103.49 97.03,105.63 97.21,105.81 97.21,107.14 96.23,108.12 90.21,108.12 88.26,106.16 88.26,105.95 88.61,105.6 88.61,105.06 88.83,104.84 U85.24
  BOTTOM w0.147: v1(96.56,103.03) 97.07,103.53 98.57,103.53 99.07,103.03 R505.1
ICSSM_MII1_TXD1: length 15.3
  TOP w0.147: U85.14 v1(94.14,104.34)
  BOTTOM w0.147: U88.27 86.73,103.34 86.9,103.16 86.9,102.91 87.09,102.73 87.33,102.73 87.49,102.89 87.49,103.44 88.01,103.95 88.01,104.65 88.18,104.82 88.42,104.82 88.6,104.65 88.6,103.51 88.77,103.34 89.41,103.34 89.67,103.6 89.67,104.06 89.8,104.18 90.05,104.18 90.2,104.03 90.2,103.78 90.39,103.6 92.68,103.6 92.88,103.39 92.88,103.09 93.03,102.94 93.32,102.94 93.53,103.15 93.53,104.15 93.71,104.34 v1(94.14,104.34)
ICSSM_MII1_TXD1_ADD: length 47
  TOP w0.147: R514.1 76.87,75.71 77.31,76.15 77.84,76.15 v1(78.31,75.68) ; v1(89.06,105.34) U85.23
  L08_SIG2 w0.091: v1(89.06,105.34) 88.06,104.33 86.16,104.33 85.56,103.73 85.56,103.19 84.71,102.33 82.59,102.33 82.15,101.89 82.15,100.49 82.52,100.11 84.99,100.11 85.22,99.88 85.22,99.19 85.02,98.99 82.34,98.99 81.68,98.33 80.43,98.33 79.99,97.89 79.99,94.85 78.21,93.07 78.21,80.19 76.71,78.68 76.71,77.77 77.11,77.37 77.11,76.5 77.46,76.14 77.85,76.14 78,75.99 78,75.99 v1(78.31,75.68)
ICSSM_MII1_TXD1_ON: length 20.2
  TOP w0.147: U85.22 89.65,105.84 89.3,106.18 v1(89.3,106.55)
  L03_SIG1 w0.091: v1(89.3,106.55) 89.52,106.55 90.22,105.85 90.36,105.85 90.47,105.96 90.47,106.45 90.57,106.56 90.73,106.56 90.83,106.45 90.83,105.96 90.94,105.85 91.09,105.85 91.2,105.96 91.2,106.45 91.31,106.56 91.46,106.56 91.56,106.45 91.56,105.96 91.67,105.85 91.82,105.85 91.93,105.96 91.93,106.45 92.04,106.56 92.19,106.56 92.3,106.45 92.3,105.96 92.4,105.85 92.7,105.85 92.86,106 92.86,107.09 93.07,107.3 94.27,107.3 94.4,107.18 94.4,106.95 94.29,106.84 93.88,106.84 93.64,106.6 93.64,105.1 93.91,104.83 95.76,104.83 v1(96.56,104.02)
  BOTTOM w0.147: R506.1 99.07,104.02 98.57,104.52 97.07,104.52 v1(96.56,104.02)
ICSSM_MII1_TXD2: length 15.3
  TOP w0.147: U85.15 94.55,104.84 v1(95.05,105.34)
  BOTTOM w0.147: v1(95.05,105.34) 94.53,104.82 93.2,104.82 92.99,104.61 90.07,104.61 89.73,104.95 89.73,105.88 89.51,106.09 87.56,106.09 87.27,105.8 87.27,104.93 87.58,104.61 87.58,104.29 87.27,103.97 86.89,103.97 86.57,104.29 86.55,104.29 86.51,104.34 U88.25
ICSSM_MII1_TXD2_ADD: length 47.3
  TOP w0.147: U85.21 v1(90.85,107.07) ; R515.1 76.87,76.91 77.12,77.16 77.82,77.16 v1(78.31,76.67)
  L08_SIG2 w0.091: v1(90.85,107.07) 90.51,106.73 90.51,106.39 91.02,105.88 92.66,105.88 92.97,105.57 92.97,105.29 92.24,104.56 88.71,104.56 87.45,103.3 86.1,103.3 85.53,102.73 85.53,95.29 84.37,94.13 81.18,94.13 78.48,91.44 78.48,80.15 77.03,78.69 77.03,77.95 v1(78.31,76.67)
ICSSM_MII1_TXD2_ON: length 19.8
  TOP w0.147: v1(90.04,106.97) 90.04,107.35 90.22,107.53 91.09,107.53 91.35,107.27 U85.20
  L03_SIG1 w0.091: v1(90.04,106.97) 90.72,107.64 94.43,107.64 94.72,107.36 94.72,105.98 94.91,105.8 95.23,105.8 95.41,105.98 95.41,107.43 95.63,107.64 97.4,107.64 97.75,107.29 97.75,105.69 97.08,105.01 v1(96.56,105.01)
  BOTTOM w0.147: v1(96.56,105.01) 99.08,105.01 R507.1
ICSSM_MII1_TXD3: length 15
  TOP w0.147: U85.16 v1(94.14,105.34)
  BOTTOM w0.147: v1(94.14,105.34) 93.12,105.34 92.72,104.94 90.42,104.94 90.17,105.18 90.17,105.57 91.33,106.72 91.33,107.34 91.1,107.56 89.62,107.56 88.74,106.68 87.08,106.68 86.83,106.43 86.83,105.65 86.52,105.34 U88.23
ICSSM_MII1_TXD3_ADD: length 47.3
  TOP w0.147: v1(78.25,78.44) 78.2,78.39 78.02,78.39 77.61,77.98 R516.1 ; U85.19 v1(91.85,107.07)
  L08_SIG2 w0.091: v1(78.25,78.44) 78.76,78.95 78.76,91.32 81.29,93.86 84.48,93.86 85.82,95.19 85.82,101.66 86.34,102.18 86.93,102.18 88.52,103.77 88.52,103.98 88.83,104.29 89.57,104.29 90.42,103.44 92.59,103.44 92.97,103.81 92.97,104.91 93.95,105.88 95.16,105.88 95.38,106.11 95.38,106.68 94.99,107.07 v1(91.85,107.07)
ICSSM_MII1_TXD3_ON: length 20.2
  TOP w0.147: v1(96.56,106) 96.85,106.29 96.85,106.53 96.7,106.68 96.46,106.68 96.04,106.26 96.04,102.71 95.89,102.57 95.69,102.57 95.54,102.72 95.54,105.97 95.39,106.12 94.89,106.12 94.71,106.29 94.71,106.53 94.93,106.74 95.75,106.74 95.87,106.86 95.87,107.07 95.71,107.23 93.58,107.23 93.45,107.1 93.45,106.71 93.32,106.58 93.14,106.58 93.01,106.71 93.01,107.1 92.88,107.23 92.53,107.23 92.35,107.06 U85.18
  BOTTOM w0.147: v1(96.56,106) 97.05,105.51 98.6,105.51 R508.1
ICSSM_MII1_TXEN: length 15.1
  TOP w0.147: v1(95.05,103.34) 94.55,102.84 U85.11
  L03_SIG1 w0.091: v1(95.05,103.34) 94.6,102.89 93.94,102.89 93.47,103.36 93.47,103.75 92.65,104.56 90.45,104.56 89.25,105.76 89.24,105.76 89.24,105.76 88.96,105.76 87.6,107.12 v1(85.09,107.12)
  BOTTOM w0.147: v1(85.09,107.12) 84.59,106.62 U88.21
ICSSM_MII1_TXEN_ADD: length 46.7
  TOP w0.147: v1(70.48,99.82) 74.55,99.82 76.37,101.63 76.37,102.92 80.44,106.99 82.06,106.99 82.74,106.31 84.66,106.31 85.06,105.9 85.64,105.9 86.04,106.31 86.77,106.31 87.02,106.06 87.02,102.83 87.51,102.34 U85.29 ; R511.1 v1(69.44,82.81)
  L03_SIG1 w0.091: v1(70.48,99.82) 72,98.29 72,89.48 70.35,87.83 70.35,84.62 69.44,83.71 v1(69.44,82.81)
ICSSM_MII1_TXEN_ON: length 19.8
  TOP w0.147: U85.28 v1(89.06,102.84)
  L08_SIG2 w0.091: v1(89.06,102.84) 90.54,101.36 92.64,101.36 92.93,101.06 92.93,99.12 93.71,98.34 95.6,98.34 95.85,98.58 95.85,99.07 95.61,99.31 93.8,99.31 93.52,99.59 93.52,100.07 93.81,100.36 96.11,100.36 v1(96.56,99.9)
  BOTTOM w0.147: R503.1 98.31,99.9 97.81,100.4 97.07,100.4 v1(96.56,99.9)
IO_EXP_INTN: length 2.4
  BOTTOM w0.147: U60.32 57.96,72.86 58.3,73.21 58.89,73.21 59.29,73.6 R395.1
JTAG_MUX1_OE#: length 4.6
  TOP w0.147: R189.1 C178.2 39.97,62.76 39.68,63.04 U30.15
JTAG_MUX_SEL: length 4.2
  TOP w0.147: SW1.1 30.11,64.75 29.98,64.62 R188.1 30.11,64.03 30.44,63.69 U30.1
JTAG_TDO2/GPIO_1: length 2.7
  BOTTOM w0.147: U35.22 R245.1 R233.1
LED2_2: length 27.7
  TOP w0.147: v1(106.6,85.09) 106.6,84.2 103.11,80.71 101.47,80.71 99.89,79.13 99.05,79.13 v1(98.08,78.16)
  BOTTOM w0.147: U35.45 90.42,73.08 90.7,73.35 90.7,77.68 91.31,78.29 R241.1 91.31,78.92 91.54,79.16 93.09,79.16 93.87,78.38 R229.2 95.18,78.38 95.4,78.16 v1(98.08,78.16) ; v1(106.6,85.09) 106.6,84.64 106.44,84.48 R221.1
LIN2_RXD: length 25.5
  TOP w0.147: v1(52,60.27) 50,60.27 48.51,61.77 48.51,62.87 47.72,63.66 U20.4 ; U1.B8 v1(58.58,46.43)
  L03_SIG1 w0.091: v1(52,60.27) 52,57.68 57.2,52.48 57.2,50.46 58.39,49.26 58.39,48.15 58.19,47.95 58.19,46.82 v1(58.58,46.43)
LIN2_TXD: length 23.1
  TOP w0.147: v1(52.58,59.29) 49.46,59.29 47.05,61.71 U20.7 ; U1.A8 v1(58.58,47.23)
  L03_SIG1 w0.091: v1(52.58,59.29) 52.84,59.03 52.84,57.2 57.5,52.54 57.5,50.56 58.9,49.16 58.9,47.55 v1(58.58,47.23)
LIN_EN: length 1.9
  TOP w0.147: R285.1 U45.2
LIN_MUX_OE#: length 2.5
  BOTTOM w0.147: U44.15 35.98,67.83 36.55,68.41 R280.1
LIN_MUX_SEL: length 43.4
  TOP w0.147: v1(27.54,66.42) 28.98,67.85 41.17,67.85 45.86,72.55 48.35,72.55 49.5,71.39 51.94,71.39 52.51,70.82 52.51,70 54.88,67.63 56.19,67.63 56.97,66.86 56.97,66.34 56.35,65.73 v1(55.46,65.73)
  BOTTOM w0.147: v1(27.54,66.42) 27.09,66.42 26.92,66.59 R277.2 ; R279.1 26.92,67.91 26.92,67.9 R277.2 ; U44.1 27.69,67.18 27.57,67.3 R277.2 ; U60.14 v1(55.46,65.73)
LIN_UART1_RXD: length 8.6
  TOP w0.147: R284.1 v1(27.14,63.08)
  BOTTOM w0.147: v1(27.14,63.08) 28.01,63.08 30.07,65.14 30.07,67.58 29.82,67.83 U44.2
LIN_UART1_TXD: length 3.7
  TOP w0.147: v1(27.55,69.78) 27.1,69.78 26.17,68.85 R283.1
  BOTTOM w0.147: U44.5 v1(27.55,69.78)
LM3488_COMP: length 5.9
  BOTTOM w0.147: U5.2 82.05,16.26 82.57,16.78 C22.1 C23.1
LM3488_DR: length 10.7
  TOP w0.147: v1(79.5,21.45) 79.83,21.78 U6.4
  BOTTOM w0.147: v1(79.5,21.45) 83,21.45 83.69,20.76 83.69,17.44 84.22,16.91 U5.6
LM3488_FB: length 3.1
  BOTTOM w0.147: R21.1 R26.2 U5.3
LM3488_ISEN: length 1.8
  BOTTOM w0.147: R22.1 U5.1
MCAN1_STB: length 89.1
  TOP w0.147: U29.14 17.93,21.91 17.66,21.63 R466.2 v1(16.38,21.63)
  L08_SIG2 w0.091: v1(18.25,38.08) 17.64,38.69 17.64,54.03 21.44,57.83 21.44,60.43 26.63,65.62 38.32,65.62 39.15,66.45 40.56,66.45 41.12,67.01 51.03,67.01 v1(52.75,68.74)
  BOTTOM w0.147: U60.18 v1(52.75,68.74) ; v1(18.25,38.08) 18.25,36.5 14.29,32.54 10.82,32.54 10.16,31.88 10.16,27.37 11.08,26.46 14.98,26.46 16.38,25.05 v1(16.38,21.63)
MCAN4_CAN_H: length 9.9
  TOP w0.104: U29.13 18.04,22.41 17.92,22.53 16.08,22.53 R171.1 15.09,22.59 13.58,22.59 13.33,22.34 13.33,20.31 13.08,20.05 J5.1
MCAN4_CAN_L: length 9.6
  TOP w0.104: U29.12 18.04,22.91 17.92,22.78 16.08,22.78 R174.2 15.22,22.85 15.2,22.85 15.19,22.84 13.59,22.84 13.33,23.1 13.33,24.88 13.08,25.13 11.55,25.13
MCAN4_RX: length 10
  TOP w0.147: v1(30.22,29.2) 28.31,29.2 26.96,27.85 26.96,23.91 26.88,23.83 R173.1
  BOTTOM w0.147: v1(30.22,29.2) 30.2,29.22 U33.2
MCAN4_RX_R: length 4.3
  TOP w0.147: R173.2 24.84,23.05 24.49,23.41 U29.4
MCAN4_T: length 7
  TOP w0.147: R174.1 C176.1 v1(14.75,25.28) ; v1(14.75,21.09) R171.2
  BOTTOM w0.147: v1(14.75,25.28) v1(14.75,21.09)
MCAN4_TX: length 24.6
  TOP w0.147: R172.2 v1(19.05,20.05)
  BOTTOM w0.147: U33.5 27.1,31.17 25.76,32.51 18.88,32.51 17.93,31.56 17.93,27.11 19.05,26 v1(19.05,20.05)
MCAN4_TX_R: length 2.9
  TOP w0.147: R172.1 20.61,21.62 20.9,21.91 U29.1
MCAN_EN: length 2.6
  TOP w0.147: R1647.2 23.84,25.58 22.66,24.41 U29.6
MDIO0_MDC: length 26.9
  TOP w0.147: U1.M17 v1(66.58,37.63)
  L03_SIG1 w0.091: v1(74.41,33.45) 73.39,34.48 73.39,37.91 74.08,38.6 76.04,38.6 v1(77.4,37.24)
  BOTTOM w0.147: U81.3 75.14,28.88 74.41,29.61 R436.2 v1(74.41,33.45) 70.85,37.01 67.2,37.01 v1(66.58,37.63) ; U90.3 v1(77.4,37.24)
MDIO0_MDIO: length 26.6
  TOP w0.147: U1.N16 v1(65.78,36.83)
  L03_SIG1 w0.091: v1(73.43,33.45) 72.91,33.98 72.91,37.97 74.16,39.23 v1(76.9,39.23)
  BOTTOM w0.114: v1(65.78,36.83) 66.18,36.43 66.82,36.43
  BOTTOM w0.147: U81.7 72.79,28.38 73.43,29.03 R437.2 v1(73.43,33.45) 70.27,36.61 67.18,36.61 66.99,36.43 66.82,36.43 ; U90.7 v1(76.9,39.23)
MDIO/MDC_MUX_SEL1: length 116.4
  TOP w0.147: v1(83.61,30.68) 83.61,28.44 82.7,27.53 81.95,27.53 80.63,26.21 69.1,26.21 66.01,23.12 61.92,23.12 61.12,22.32 51.1,22.32 47.68,25.74 45.54,25.74 v1(43.67,27.61) ; v1(40.47,32.79) 39.3,33.96 39.3,36.15 38.63,36.82 37.97,36.82 37.67,37.12 37.67,40.37 38.22,40.91 38.58,40.91 39.3,41.62 39.3,43.76 40.17,44.64 40.17,47.31 44.91,52.04 44.91,54.15 46.11,55.35 46.11,56.09 44.77,57.43 44.77,59.04 43.53,60.27 43.53,61.44 43.99,61.9 43.99,68.79 45.34,70.14 47.23,70.14 47.71,69.65 v1(51.86,69.65)
  BOTTOM w0.147: v1(43.67,27.61) 43.67,30.74 41.62,32.79 v1(40.47,32.79) ; v1(83.61,30.68) 79.49,30.68 78.82,31.36 R474.1 U81.1 ; U60.19 52.28,69.24 v1(51.86,69.65)
MDIO/MDC_MUX_SEL2: length 117.8
  TOP w0.147: v1(39.45,32.79) 38.64,33.61 38.64,34.93 37.38,36.19 37.38,40.49 38.09,41.2 38.46,41.2 39,41.74 39,43.88 39.88,44.76 39.88,47.43 44.62,52.17 44.62,54.27 45.82,55.47 45.82,55.96 44.47,57.31 44.47,57.85 42.49,59.84 42.49,60.42 42.95,60.88 42.95,62.02 42.56,62.4 42.56,68.74 45.96,72.14 47.73,72.14 49.32,70.55 v1(52,70.55) ; v1(44.38,28.33) 45.7,27 54.4,27 54.98,26.42 57.7,26.42 58.24,26.96 66.57,26.96 67.02,26.51 80.51,26.51 81.83,27.82 82.58,27.82 83.1,28.35 83.1,31.09 v1(83.61,31.59)
  BOTTOM w0.147: U60.20 52.8,69.74 52,70.54 v1(52,70.55) ; v1(39.45,32.79) 39.98,33.32 41.81,33.32 44.38,30.74 v1(44.38,28.33) ; v1(83.61,31.59) 83.29,31.27 79.74,31.27 78.4,32.61 R3871.2 U90.1
MMC0_CLK: length 1.7
  TOP w0.147: v1(51.07,48.23) 51.07,48.41 RA2.4
  BOTTOM w0.147: v1(51.07,48.23) 51.07,48.65 R123.1
MMC0_CLK_R: length 39.6
  TOP w0.147: R132.2 28.68,51.53 v1(29.33,52.18)
  L03_SIG1 w0.091: v1(52.6,49.77) 46.81,49.77 45.96,48.92 45.96,48.02 45.71,47.76 45.35,47.76 44.58,47.76 44.14,48.21 44.14,49.58 43.6,50.11 43.6,52.94 43.6,53.17 42.88,53.89 31.22,53.89 31.21,53.88 31.03,53.88 v1(29.33,52.18)
  BOTTOM w0.147: v1(52.6,49.77) R134.1 R123.2 ; U24.6 29.18,51.28 29.33,51.43 v1(29.33,52.18) 28.76,52.76 26.32,52.76 25.79,52.23 J4.5
MMC0_CMD: length 40.7
  TOP w0.147: R131.2 26.41,51.3 v1(26.92,50.79) ; RA4.3 46.35,48.51 46.61,48.24 v1(46.69,48.24)
  L03_SIG1 w0.091: v1(26.92,50.79) 25.64,50.79 25.55,50.88 25.55,52.35 25.63,52.43 25.74,52.43 25.82,52.35 25.82,51.39 25.9,51.31 26.02,51.31 26.1,51.39 26.1,52.35 26.18,52.43 26.29,52.43 26.37,52.35 26.37,51.39 26.45,51.31 26.57,51.31 26.65,51.39 26.65,52.35 26.73,52.43 26.84,52.43 26.92,52.35 26.92,51.39 27.13,51.17 30.19,51.17 32.36,53.34 41.68,53.34 42.96,52.07 42.96,49.98 43.59,49.35 43.59,47.98 44.35,47.21 45.58,47.21 46.03,47.21 46.69,47.87 v1(46.69,48.24)
  BOTTOM w0.147: J4.3 26.16,50.03 v1(26.92,50.79) 26.92,50.78 U24.3
MMC0_DAT0: length 42.7
  TOP w0.147: v1(29.97,51.68) 29.46,51.17 29.46,50.34 29.01,49.9 R127.2 ; RA2.3 49.9,48.51 50.16,48.24 v1(50.23,48.24)
  L03_SIG1 w0.091: v1(50.23,48.24) 49.8,48.67 47.74,48.67 47.62,48.79 47.62,48.92 47.75,49.05 48.6,49.05 48.7,49.15 48.7,49.31 48.58,49.42 46.97,49.42 46.26,48.72 46.26,47.85 45.9,47.49 45.47,47.49 44.47,47.49 43.86,48.09 43.86,49.46 43.33,50 43.33,53.06 42.77,53.62 32.25,53.62 32.24,53.61 31.33,53.61 29.97,52.25 v1(29.97,51.68)
  BOTTOM w0.147: J4.7 25.16,54.43 26.36,53.23 29.28,53.23 29.97,52.54 v1(29.97,51.68) 29.97,51.04 29.71,50.78 U24.7
MMC0_DAT1: length 42.2
  TOP w0.147: v1(29.97,50.15) 29.97,49.64 29.24,48.92 R128.2 ; 49.4,48.94 49.4,48.51 v1(49.14,48.25)
  L03_SIG1 w0.091: v1(49.14,48.25) 48.2,47.3 47.36,47.3 46.4,46.34 43.79,46.34 41.14,48.98 41.14,51.97 40.85,52.26 39.44,52.26 38.01,50.83 35.33,50.83 35.25,50.75 35.25,50.64 35.33,50.56 36.57,50.56 36.65,50.48 36.65,50.36 36.57,50.28 34.84,50.28 34.29,50.83 32.15,50.83 31.47,50.15 v1(29.97,50.15)
  BOTTOM w0.147: U24.8 29.76,50.28 29.77,50.28 29.84,50.28 v1(29.97,50.15) 30.29,50.47 30.29,50.6 30.52,50.84 30.52,52.55 29.33,53.74 26.94,53.74 25.16,55.53 J4.8
MMC0_DAT2: length 41.7
  TOP w0.147: R129.2 26.85,48.76 26.97,48.88 v1(27.43,48.88) ; v1(48.26,48.25) 48.26,48.43 RA2.1
  L03_SIG1 w0.091: v1(48.26,48.25) 47.63,47.63 47.26,47.63 46.24,46.61 43.9,46.61 42.28,48.23 42.28,51.97 41.71,52.54 39.21,52.54 37.86,51.19 31.73,51.19 31.16,50.62 28.25,50.62 27.85,50.22 27.85,49.95 27.93,49.87 29.31,49.87 29.39,49.79 29.39,49.67 29.31,49.59 27.93,49.59 27.85,49.51 27.85,49.4 27.93,49.32 29.31,49.32 29.39,49.24 29.39,48.59 29.1,48.3 27.59,48.3 27.43,48.46 v1(27.43,48.88)
  BOTTOM w0.147: J4.1 26.38,47.83 v1(27.43,48.88) 27.81,49.26 U24.1
MMC0_DAT3: length 40.8
  TOP w0.147: v1(47.45,48.24) 47.37,48.33 47.37,48.56 RA4.4 ; v1(26.92,49.77) 26.67,50.03 R130.2
  L03_SIG1 w0.091: v1(26.92,49.77) 28.05,50.9 30.79,50.9 31.96,52.07 36.12,52.07 36.21,51.98 36.21,51.86 36.12,51.77 32.41,51.77 32.31,51.68 32.31,51.56 32.41,51.47 37.59,51.47 39.02,52.9 41.74,52.9 42.65,51.99 42.65,48.4 44.11,46.94 45.69,46.94 46.15,46.94 v1(47.45,48.24)
  BOTTOM w0.147: U24.2 27.43,50.28 v1(26.92,49.77) 26.08,48.93 J4.2
MMC0_SDCD: length 38.7
  TOP w0.147: 45.85,48.94 45.85,48.51 v1(45.53,48.19)
  L03_SIG1 w0.091: v1(45.53,48.19) 45.53,48.73 44.01,50.25 44.01,53.16 42.21,54.96 33.87,54.96 30.22,58.62 30.11,58.62 30.03,58.54 30.03,58.42 33.14,55.31 33.14,55.2 33.06,55.12 32.84,55.12 v1(29.54,58.41)
  BOTTOM w0.147: v1(29.54,58.41) 29.54,57.76 U25.5 27.28,57.75 26.81,57.28 R133.2 J4.9
MMC0_WP: length 3
  TOP w0.147: RA4.1 44.7,48.43 v1(44.7,48.25)
  BOTTOM w0.147: v1(44.7,48.25) 43.97,48.25 R124.1 43.96,47.52 43.97,47.51 TP48.1
MUX_UART1/LIN_RXD: length 42.7
  TOP w0.147: R143.2 v1(58.99,51.73)
  BOTTOM w0.147: U44.4 30.04,69.13 32.42,66.75 32.42,59.23 33.86,57.79 48.96,57.79 52.54,54.21 56.52,54.21 v1(58.99,51.73)
MUX_UART1/LIN_TXD: length 49.7
  BOTTOM w0.147: U44.7 25.95,71.08 24.79,69.91 24.79,64.5 29.46,59.83 31.01,59.83 33.34,57.5 48.68,57.5 52.45,53.73 55.55,53.73 58.4,50.88 R145.2
OPSI_DQS: length 4.6
  TOP w0.147: U19.C3 v1(32.35,43.16)
  BOTTOM w0.147: R111.1 R112.1 R114.1 R113.1 32.47,43.28 v1(32.35,43.16)
OSC0: length 6.1
  BOTTOM w0.147: Y2.1 26.52,81.99 25.52,82.99 25.52,84.53 25.77,84.78 C269.2 25.77,85.97 25.54,86.2 U52.88
OSC1: length 4.1
  BOTTOM w0.147: Y2.3 24.75,83.92 C270.2 24.75,85.97 25.14,86.36 U52.89
OSC_CLK_OUT: length 1.4
  TOP w0.147: R273.1 U42.3
OSPI/QSPI_MUX_SEL: length 37.4
  TOP w0.147: R1679.1 43.64,40.04 v1(43.68,39.99) ; U1.P16 v1(65.78,36.03)
  L08_SIG2 w0.091: v1(43.68,39.99) 44,40.31 49.73,40.31 52.59,43.17 52.59,43.39 52.82,43.62 55.54,43.62 55.77,43.39 55.77,42.27 55.54,42.04 55.24,42.04 54.99,41.79 54.99,40.67 55.87,39.79 59.37,39.79 60.03,39.13 60.03,38.83 60.82,38.04 66.72,38.04 66.97,37.79 66.97,36.67 66.72,36.42 66.17,36.42 v1(65.78,36.03)
  BOTTOM w0.147: U80.10 43.51,39.82 v1(43.68,39.99) ; v1(43.68,39.99) 44.14,39.99 R3836.1 ; v1(43.68,39.99) 43.36,40.32 U80.9
OSPI_CLK: length 25.1
  TOP w0.147: v1(35.68,39.74) 36,40.06 R110.1 34.14,40.37 U19.B2
  L03_SIG1 w0.091: v1(35.68,39.74) 35.68,36.38 36.17,35.89 36.85,35.89 36.93,35.97 36.93,36.32 37.01,36.4 37.13,36.4 37.21,36.32 37.21,35.97 37.29,35.89 37.4,35.89 37.48,35.97 37.48,36.32 37.56,36.4 37.68,36.4 37.76,36.32 37.76,35.97 37.84,35.89 39.05,35.89 39.14,35.98 39.14,36.78 39.79,37.43 39.79,37.85 39.79,37.85 39.79,41.64 39.79,41.64 39.79,42.43 39.79,42.43 39.79,43.94 41.35,45.5 41.46,45.5 v1(41.73,45.76)
  BOTTOM w0.147: U80.42 v1(41.73,45.76)
OSPI_CS0: length 21.3
  TOP w0.147: R98.1 48.92,36.83 48.05,36.83 TP45.1 v1(46.1,37.38) ; v1(36.1,42.79) R109.2 34.37,41.73 34.02,42.08 33.43,42.08 U19.C2
  L08_SIG2 w0.091: v1(46.1,37.38) 43.37,37.38 42.17,38.58 39.69,38.58 38.46,39.8 37.55,39.8 36.1,41.26 v1(36.1,42.79)
OSPI_DQ0: length 21.6
  TOP w0.147: R451.2 v1(32.6,49.39)
  L03_SIG1 w0.091: v1(32.6,49.39) 33,49.79 34.25,49.79 34.8,49.24 38.16,49.24 38.24,49.32 38.24,49.44 38.16,49.52 35.07,49.52 34.99,49.6 34.99,49.71 35.07,49.79 39.44,49.79 41.22,48 41.22,46.25 v1(40.73,45.76)
  BOTTOM w0.147: U80.40 v1(40.73,45.76) ; v1(32.6,49.39) 32.59,49.38 R100.1
OSPI_DQ1: length 22.5
  TOP w0.147: v1(37.08,44.65) R452.2
  L03_SIG1 w0.091: v1(37.08,44.65) 36.47,44.65 35.53,45.59 35.53,48.53 35.68,48.68 36.36,48.68 36.51,48.53 36.51,45.98 36.43,45.9 36.31,45.9 36.14,46.07 36.14,48.35 36.06,48.43 35.95,48.43 35.87,48.35 35.87,45.86 36.49,45.23 38.25,45.23 38.5,45.49 v1(38.5,45.98)
  BOTTOM w0.147: R101.1 37.06,43.66 37.08,43.68 v1(37.08,44.65) ; v1(38.5,45.98) 38.5,44.03 38.71,43.82 U80.37
OSPI_DQ2: length 23.4
  TOP w0.147: R102.2 v1(26.31,42.3) R453.2
  L03_SIG1 w0.091: v1(26.31,42.3) 28.09,44.09 30.58,44.09 33.13,41.54 36.72,41.54 36.8,41.62 36.8,41.74 36.72,41.82 33.98,41.82 33.9,41.9 33.9,42.01 33.98,42.09 37.43,42.09 v1(38.16,42.82)
  BOTTOM w0.147: U80.35 v1(38.16,42.82)
OSPI_DQ3: length 23
  TOP w0.147: R454.2 v1(26.31,44.84) R103.1
  L03_SIG1 w0.091: v1(38.16,41.82) 38.69,42.35 38.69,43.34 38.69,43.86 38.5,44.05 37.99,44.05 37.5,43.55 36.14,43.55 35.2,44.49 32.08,44.49 31.95,44.37 31.95,44.24 32.04,44.14 33.58,44.14 33.69,44.04 33.69,43.86 33.59,43.76 31.51,43.76 30.78,44.49 26.66,44.49 v1(26.31,44.84)
  BOTTOM w0.147: U80.33 v1(38.16,41.82)
OSPI_DQ4: length 24.6
  TOP w0.147: R455.2 v1(26.31,43.57) R104.1
  L03_SIG1 w0.091: v1(38.29,39.32) 37.91,39.32 36.11,41.12 33.92,41.12 33.84,41.04 33.84,40.92 33.92,40.84 35.82,40.84 35.9,40.76 35.9,40.65 35.82,40.57 33.64,40.57 33.56,40.65 33.56,40.65 30.52,43.69 28.86,43.69 27.04,41.87 26.13,41.87 25.88,42.12 25.88,43.14 v1(26.31,43.57)
  BOTTOM w0.147: U80.28 v1(38.29,39.32)
